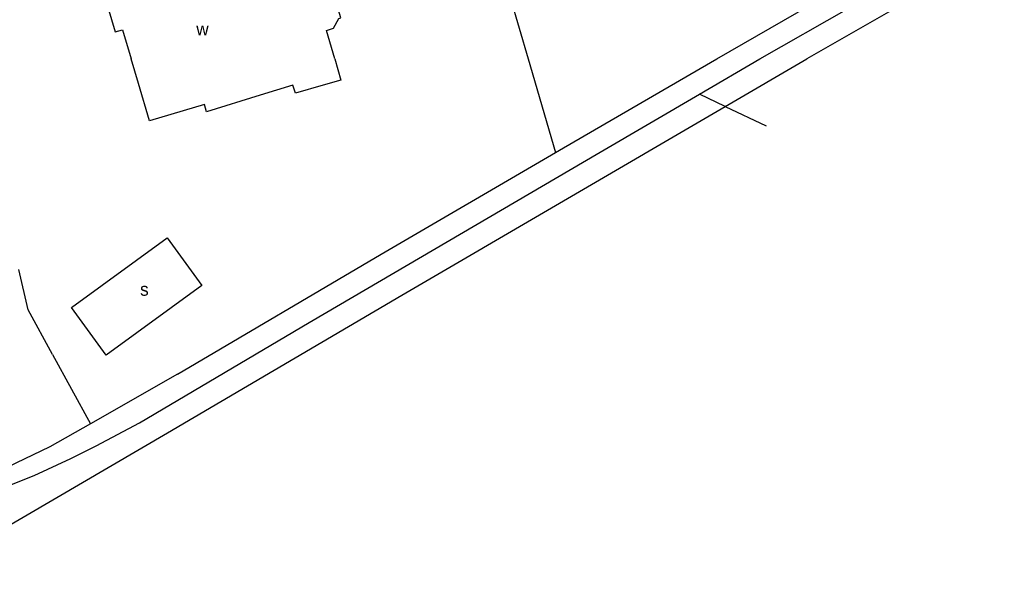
# Model space of a CAD drawing. Extents: x 162427 to 165104, y 384242 to 386287.
# Drawn here: x 163093 to 163396.3, y 384340 to 384512.2 of the extents above; entities that cross this region are included whole.
import ezdxf

# ---------------------------------------------------------------- set-up
doc = ezdxf.new("R2010")
doc.units = 0
for name, color, linetype in [('BLT_Basislijn', 7, 'Continuous'), ('BLT_Bebouwing', 7, 'Continuous'), ('BLT_Centroide', 7, 'Continuous'), ('BLT_Vlakafsluiter', 7, 'Continuous')]:
    doc.layers.add(name, color=color, linetype=linetype)

msp = doc.modelspace()

# ---------------------------------------------------------------- linework, layer by layer
at = {"layer": 'BLT_Basislijn'}
for p, q in [((163238.04, 384543), (163250.62, 384500)), ((163396.32, 384534.12), (163350, 384507.52)), ((163309.07, 384500), (163347.82, 384522.43)), ((163322.43, 384500), (163350, 384515.76)), ((163350, 384507.52), (163336.9, 384500)), ((163250.62, 384500), (163259.09, 384471.06)), ((163261.52, 384472.48), (163309.07, 384500)), ((163303.72, 384489.08), (163322.43, 384500)), ((163311.65, 384485.27), (163336.9, 384500)), ((163272.94, 384471.12), (163303.72, 384489.08)), ((163211.43, 384426.8), (163311.65, 384485.27)), ((163259.09, 384471.06), (163261.52, 384472.48)), ((163182.67, 384418.36), (163272.94, 384471.12)), ((163138.78, 384384.13), (163211.43, 384426.8)), ((163130.18, 384387.23), (163182.67, 384418.36)), ((163103.22, 384408.46), (163114.96, 384387)), ((163141.96, 384402.34), (163114.96, 384387)), ((163076.52, 384347.85), (163138.78, 384384.13))]:
    msp.add_line(p, q, dxfattribs=at)
for points in [[(163141.96, 384402.34), (163205.06, 384439.5), (163259.09, 384471.06)], [(163109.02, 384422.96), (163138.73, 384444.6), (163149.48, 384429.85), (163119.77, 384408.2), (163109.02, 384422.96)], [(163103.22, 384408.46), (163095.66, 384422.28), (163092.78, 384434.75)], [(163034.94, 384340), (163059.08, 384353.65), (163073.48, 384361.01), (163077.16, 384362.85), (163097.54, 384370.98), (163108.88, 384376.19), (163116.7, 384380.18), (163130.18, 384387.23)], [(163114.96, 384387), (163102.38, 384379.85), (163081.21, 384369.72), (163044.19, 384356.37)]]:
    msp.add_lwpolyline(points, dxfattribs=at)
at = {"layer": 'BLT_Bebouwing'}
for p, q in [((163129.8, 384492.4), (163127.57, 384500)), ((163190.62, 384500), (163192.49, 384493.46)), ((163167.55, 384488.75), (163150.92, 384483.67))]:
    msp.add_line(p, q, dxfattribs=at)
for points in [[(163118.88, 384521.04), (163122.6, 384508.4), (163124.9, 384509.07), (163127.57, 384500)], [(163190.27, 384509.54), (163191.86, 384512.52), (163192.5, 384512.71), (163191.78, 384515.14)], [(163190.62, 384500), (163188.09, 384508.87), (163190.27, 384509.54)], [(163192.49, 384493.46), (163187.03, 384491.88), (163178.45, 384489.4)], [(163150.92, 384483.67), (163150.25, 384485.91), (163133.19, 384480.88), (163129.8, 384492.4)], [(163178.45, 384489.4), (163177.69, 384491.85), (163167.55, 384488.75)]]:
    msp.add_lwpolyline(points, dxfattribs=at)
at = {"layer": 'BLT_Vlakafsluiter'}
for q in [(163303.72, 384489.08), (163324.35, 384479.33)]:
    msp.add_line((163311.65, 384485.27), q, dxfattribs=at)

# ---------------------------------------------------------------- texts
at = {"layer": 'BLT_Centroide'}
for s, p in [('w', (163147.72, 384507.3)), ('s', (163130.31, 384426.64))]:
    msp.add_text(s, height=4, dxfattribs=at).set_placement(p)

doc.saveas('drawing.dxf')
